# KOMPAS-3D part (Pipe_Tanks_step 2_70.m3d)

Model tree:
1. X Axis
2. Y Axis
3. Z Axis  (labels: Pipe Dn 50; Bend 90 Dn 50)
     Òîëùèíà ñòåíêè 1 = 1

Referenced files in C:\Documents and Settings\kashirsky\Мои документы\Camtasia Studio\Pipelines3D\Tanks\: Tanks_step 4.a3d
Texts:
  Pipe Dn 50
  Steel ASTM A295
  Three Point Plane
  Plane at Angle
  Line and Point Plane
  Axis through Two Vertices
  Axis of Feature
  Axis of Conical Surface
  Axis through Edge
  Trim by Surface
  Trim by Sketch
  Feature with No History
  Intersection Axis of Two Planes
  Two Line Plane
  Line and Face Plane
  Bend by line
  Hole in sheet body
  Cut in sheet body
  Point in CM
  Linear Dimension from Line to Point
  Surface Finish Symbol
  Geometric Tolerance Symbol
  Leader #1
  Leader #2
  Leader #3
  Shape Deviations and Datum
  Node point number
  Mark of coordination axis
  Node point designation
  Mark/Reference designation with leader
  Mark/reference designation on line
  Mark/Reference designation without leader
  Bend 90 Dn 50
  Plane of section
